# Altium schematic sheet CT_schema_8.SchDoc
size 368 x 335 mm
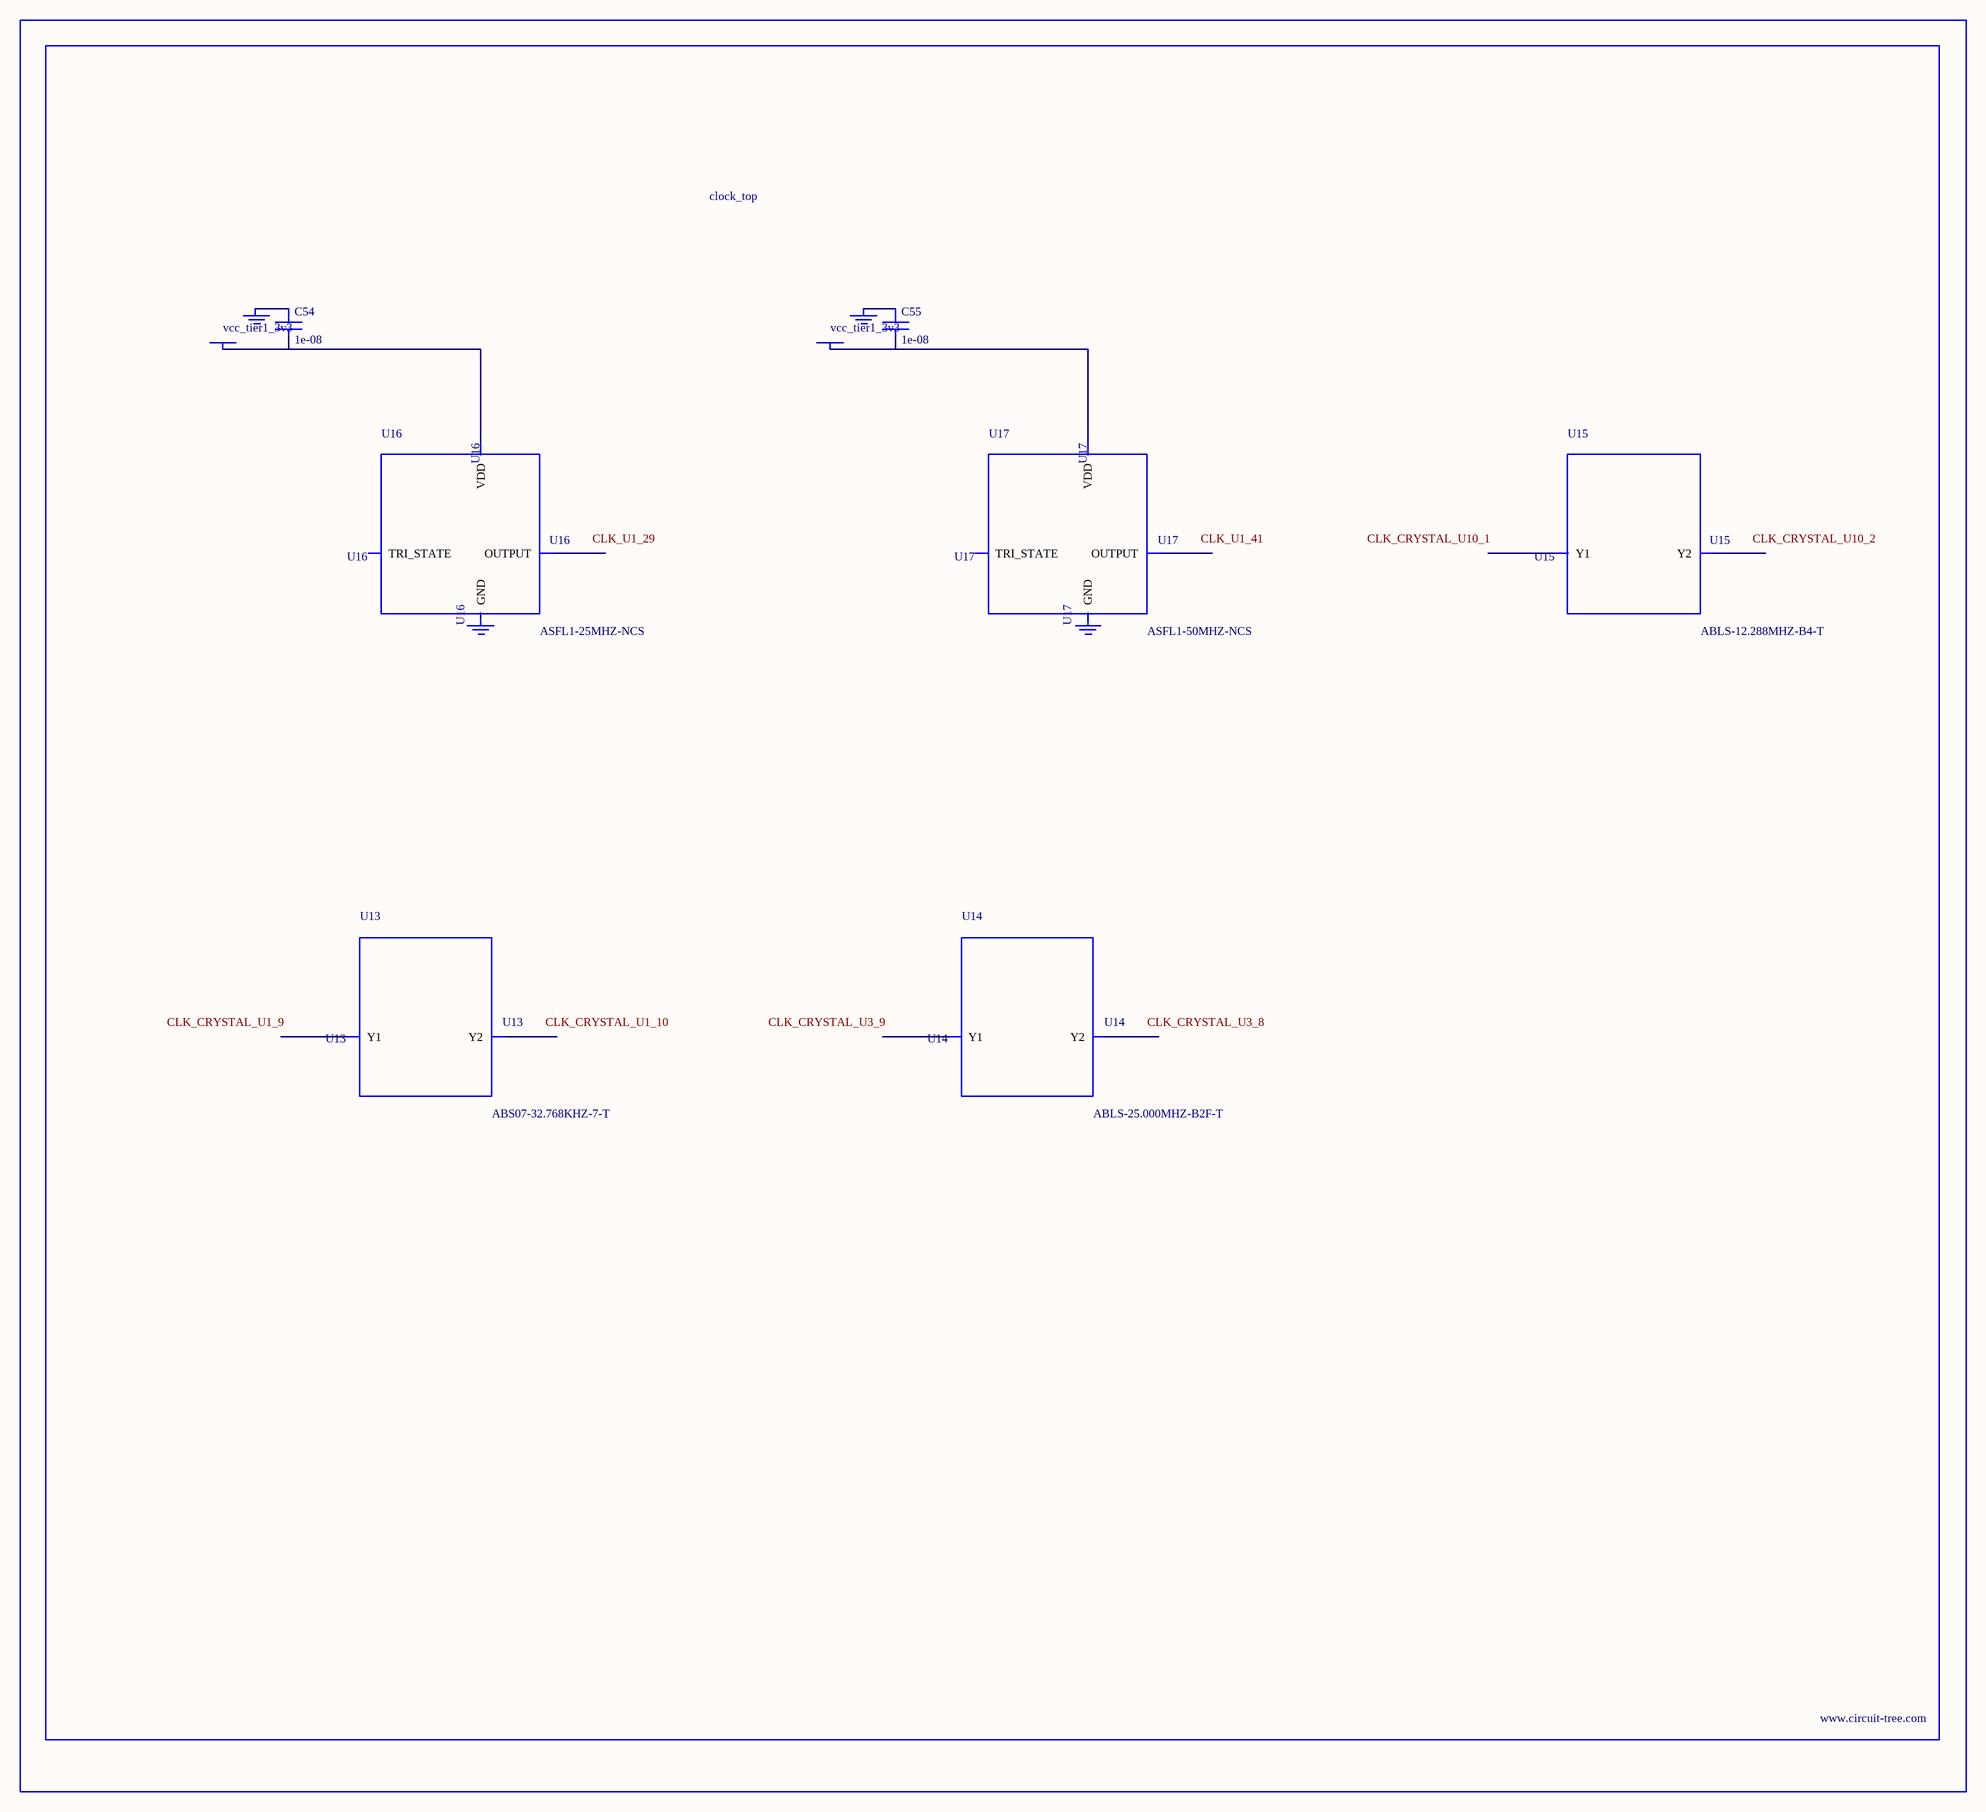
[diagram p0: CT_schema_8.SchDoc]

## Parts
BORDER7  (no value)
C54  1e-08  [C0402]
C55  1e-08  [C0402]
GND_INSTANCE_7_0  (no value)
GND_INSTANCE_7_1  (no value)
GND_INSTANCE_7_2  (no value)
GND_INSTANCE_7_3  (no value)
POWER_INSTANCE_7_0  vcc_tier1_3v3
POWER_INSTANCE_7_1  vcc_tier1_3v3
U13  ABS07-32.768KHZ-7-T  [ABS07-32.768KHZ-7-T]
U14  ABLS-25.000MHZ-B2F-T  [ABLS-25.000MHZ-B2F-T]
U15  ABLS-12.288MHZ-B4-T  [ABLS-12.288MHZ-B4-T]
U16  ASFL1-25MHZ-NCS  [ASFL1]
U17  ASFL1-50MHZ-NCS  [ASFL1]

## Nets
NetC54_1: C54.1 GND_INSTANCE_7_0.0(GND)
NetC54_2: C54.2 POWER_INSTANCE_7_0.0(PWR) U16.4(VDD)
NetC55_1: C55.1 GND_INSTANCE_7_2.0(GND)
NetC55_2: C55.2 POWER_INSTANCE_7_1.0(PWR) U17.4(VDD)

Not connected (* = marked no-connect by the designer): GND_INSTANCE_7_1 0(GND); GND_INSTANCE_7_3 0(GND); U13 1(Y1) 2(Y2); U14 1(Y1) 2(Y2); U15 1(Y1) 2(Y2); U16 1(TRI_STATE) 2(GND) 3(OUTPUT); U17 1(TRI_STATE) 2(GND) 3(OUTPUT)

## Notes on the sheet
- Labels drawn without touching a wire or pin: CLK_CRYSTAL_U1_9, CLK_CRYSTAL_U1_10, CLK_CRYSTAL_U3_8, CLK_CRYSTAL_U3_9, CLK_CRYSTAL_U10_1, CLK_CRYSTAL_U10_2, CLK_U1_29, CLK_U1_41

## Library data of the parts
BORDER7 = BORDER_PAGE7
C54 C55 = C0402C103K3RAC
GND_INSTANCE_7_0-GND_INSTANCE_7_3 = GND
POWER_INSTANCE_7_0 POWER_INSTANCE_7_1 = PWR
